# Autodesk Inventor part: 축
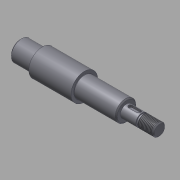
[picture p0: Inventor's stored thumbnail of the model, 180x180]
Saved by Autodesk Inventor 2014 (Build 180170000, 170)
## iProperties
Created: 2015-12
Part Number: 축
Material: 강철, 연강
Document SubType Name: Modeling
Designer: mdu
Density: 7.86 g/cm^3
Appearance: 강철
CustomPartVersion: 1
Author: mdu
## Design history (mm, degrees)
sketch "스케치5"
  geometry: L1 (0, 0)-(135, 0); L2 (0, 0)-(135, 0); L3 (135, 0)-(135, 6); L4 (103, 6)-(103, 10); L5 (103, 10)-(62, 10); L6 (62, 10)-(62, 13); L7 (62, 13)-(21, 13); L8 (21, 13)-(21, 10); L9 (21, 10)-(0, 10); L10 (0, 10)-(0, 0); L11 (118, 6)-(118, 5); L12 (118, 5)-(120, 5); L13 (120, 5)-(120, 6); L14 (135, 6)-(120, 6); L15 (118, 6)-(103, 6)
  constraints: 31 end point, 12 perpendicular, 9 parallel, 1 collinear, 1 horizontal
  dimensions: "d43" = 20 diameter of L9 L1; "d44" = 26 diameter of L7 L1; "d45" = 20 diameter of L5 L2; "d47" = 41 distance of L6.end L7.end; "d48" = 32 distance between parallel lines of L3 L4; "d50" = 21 distance of L8.end L9.end; "d52" = 12 diameter of L14 L1; "d53" = 15 distance between parallel lines of L3 L13; "d54" = 2 distance of L11.end L12.end; "d55" = 1 distance between parallel lines of L14 L12; "d64" = 135 distance of L1.start L1.end
revolve "회전4" sketch "스케치5" stored, may be unused: angle "d51" = 90 deg
feature "스레드6" dims "d56" = 10, "d57" = 0
chamfer "모따기6" distance "d32" = 1; stored, may be unused: second distance "d33" = 0.4, angle "d34" = 45 deg
chamfer "모따기5" distance "d27" = 1; stored, may be unused: second distance "d28" = 0.125, angle "d29" = 45 deg
fillet "모깎기1" dims "d17" = 0.3
fillet "모깎기2" dims "d18" = 0.3
chamfer "모따기3" distance "d19" = 1; stored, may be unused: second distance "d20" = 1, angle "d21" = 45 deg
node "작업 평면1"
sketch "스케치6"
  geometry: L1 (-3.5, 2)-(4.5, 2); L2 (4.5, -2)-(-3.5, -2); L3 (-7.5, 9)-(-7.5, -9) reference; A1 r 2 centre (4.5, 0) between (4.5, -2) and (4.5, 2); A2 r 2 centre (-3.5, 0) between (-3.5, 2) and (-3.5, -2); 1 further point
  constraints: 4 end point, 4 point on circle, 4 tangent, 2 centre point, 1 horizontal, 1 horizontal alignment, 1 parallel
  dimensions: "d59" = 2 distance edge to line of A2 L3; "d60" = 12 dimension on A1 A2; "d61" = 4 distance between parallel lines of L2 L1
extrude "돌출1" cut sketch "스케치6" distance "d62" = 2.3; taper "d63" = 0 deg
node "솔리드1"
node "솔리드2"
other parameters: "d46" = 12
